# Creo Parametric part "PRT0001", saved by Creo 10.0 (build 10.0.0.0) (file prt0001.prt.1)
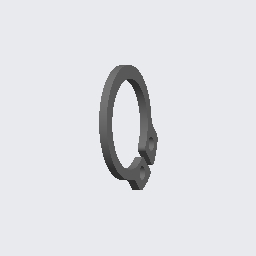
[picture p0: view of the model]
Units: millimeter Newton Second (mmNs); MM, TONNE, SECS

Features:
  1. coordinate system "61741200"
  2. imported feature "Import-ke ID 4"

Other named items: NOTE_0

Notes: 61741200

Surfaces: 16 cylinder, 6 plane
